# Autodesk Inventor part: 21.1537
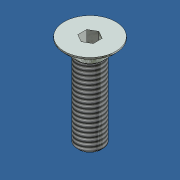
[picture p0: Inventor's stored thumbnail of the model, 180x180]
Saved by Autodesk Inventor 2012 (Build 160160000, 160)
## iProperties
Created: 2006-12
Part Number: 21.1537
Material: Steel, Mild
Description: M5X18 C'SUNK
Document SubType Name: Modeling
Standard: DIN 7991
Designer: Andy Moles
Standards Organization: DIN
Language: en-US
Size Designation: M5x16
Categories: <MemberInstance Version="R10.0.0"><Categories><Category DisplayName="Fasteners" InternalName="e4da775c-781d-43d5-af7c-5136215cf5a6" Mnemonic="FSTN"><Category Di
Density: 7.86 g/cm^3
Author: Andy Moles
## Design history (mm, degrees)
node "Sketch1"
node "WorkPoint1"
sketch "Sketch2"
  geometry: L1 (-2.5, -18)-(0, -18); L2 (-2.5, -2.8)-(-2.5, -18); L3 (-5, -0.3)-(-2.5, -2.8); L4 (-5, 0)-(-5, -0.3); L5 (0, 0)-(-5, 0); L6 (0, -18)-(0, 0); L7 (0, -18)-(0, 0); L8 (0, -17.6)-(0, 4.8) reference; L9 (0.5, 0)-(-6.5, 0) reference
  constraints: 14 end point, 3 vertical, 2 horizontal
  dimensions: "d1" = 45 deg angle of L3 L6; "d3" = 5 distance of L5.start L4.start (= 0.5 x dk); "d5" = 2.5 distance of L1.start L1.end (= 0.5 x NND); "d7" = 18 distance of L1.end L5.start (= NLG); "ParC" = 0.3 distance of L4.start L3.start; "d22" = 0 distance between parallel lines of L8 L6; "d23" = 0 distance between parallel lines of L9 L5
fillet "Fillet1" dims "d18" = 0.2 (= r)
chamfer "Chamfer1" distance "d19" = 0.4 (= 0.5 x PTC); stored, may be unused: angle "d20" = 45 deg, second distance "d39" = 0.4 (= 0.5 x PTC)
node "MSC_A1"
node "MSC_PF1"
node "MSC_PT1"
body "Solid1"
revolve "Revolution1" stored, may be unused: angle "d8" = 360 deg
sketch "Sketch3"
  geometry: L1 (-1.5, 0.866)-(-1.5, -0.866); L2 (0, 1.732)-(-1.5, 0.866); L3 (1.5, 0.866)-(0, 1.732); L4 (1.5, -0.866)-(1.5, 0.866); L5 (0, -1.732)-(1.5, -0.866); L6 (-1.5, -0.866)-(0, -1.732); C1 r 1.5 at (0, 0); C2 r 2.5 at (0, 0) reference
  constraints: 12 end point, 6 tangent, 2 parallel, 2 vertical, 1 centre point, 1 concentric
  dimensions: "d11" = 3 diameter of C1 (= ParS); "d13" = 120 deg angle of L1 L2; "d15" = 120 deg angle of L6 L1
extrude "Extrusion1" cut sketch "Sketch3" distance "d16" = 2.3 (= ParT); taper "d17" = 0 deg
thread "Thread1" dims "d35" = 0, "b" = 15.5
other parameters: "NND" = 5 [user parameter; used in 2 equation terms], "PTC" = 0.8 [user parameter; used in 2 equation terms], "ParK" = 2.8 [user parameter], "ParS" = 3 [user parameter; used in 1 equation term], "ParT" = 2.3 [user parameter; used in 1 equation term], "r" = 0.2 [user parameter; used in 1 equation term], "NLG" = 18 [user parameter; used in 1 equation term], "d0" = 45 deg (derived), "d2" = 3 (derived), "d4" = 1.5 (derived), "d6" = 8 (derived), "d9" = 0, "d10" = 2 (derived), "d12" = 120 deg (derived), "d14" = 120 deg (derived), "d37" = 0, "d38" = 0, "d40" = 0, "d41" = 0, "d42" = 0, "THREADDIA" = 5 (= NND) [user parameter]
